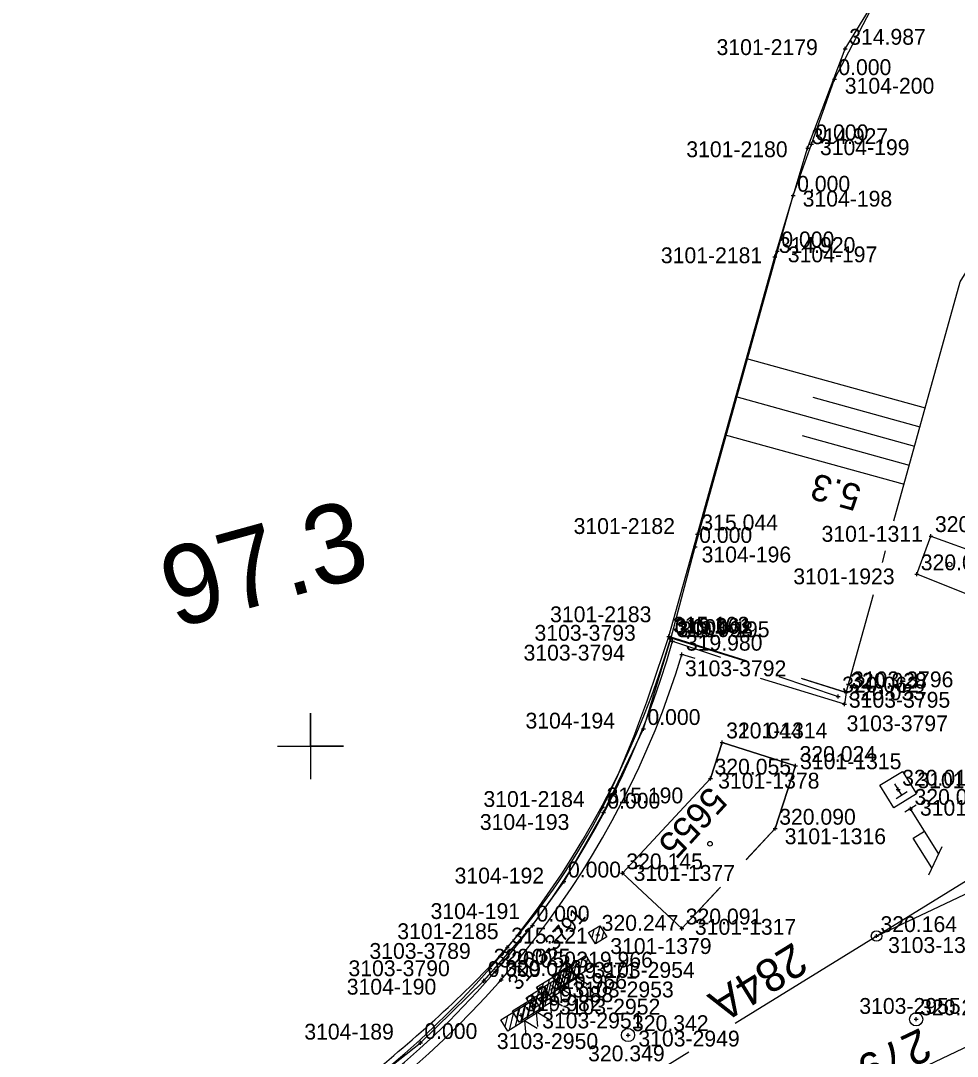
# Model space of a CAD drawing. Extents: x -821875 to -821475, y -1070280 to -1069975.
# Drawn here: x -821810.98 to -821775.51, y -1070211.76 to -1070172.51 of the extents above; entities that cross this region are included whole.
import ezdxf

# ---------------------------------------------------------------- set-up
doc = ezdxf.new("R2010")
doc.units = 0
for name, color, linetype in [('Vrstva 1', 7, 'Continuous'), ('Vrstva 10', 7, 'Continuous'), ('Vrstva 11', 7, 'Continuous'), ('Vrstva 13', 7, 'Continuous'), ('Vrstva 17', 7, 'Continuous'), ('Vrstva 2', 7, 'Continuous'), ('Vrstva 23', 7, 'Continuous'), ('Vrstva 28', 7, 'Continuous'), ('Vrstva 3', 7, 'Continuous'), ('Vrstva 33', 7, 'Continuous'), ('Vrstva 48', 7, 'Continuous'), ('Vrstva 49', 7, 'Continuous'), ('Vrstva 52', 7, 'Continuous'), ('Vrstva 53', 7, 'Continuous'), ('Vrstva 57', 7, 'Continuous'), ('Vrstva 59', 7, 'Continuous'), ('Vrstva 60', 7, 'Continuous'), ('Vrstva 61', 7, 'Continuous'), ('Vrstva 7', 7, 'Continuous')]:
    doc.layers.add(name, color=color, linetype=linetype)

# ---------------------------------------------------------------- blocks, each defined once
blk = doc.blocks.new('BOD')
at = {"layer": 'Vrstva 3'}
for p, q in [((-0.15, 0), (0.15, 0)), ((0, -0.15), (0, 0.15))]:
    blk.add_line(p, q, dxfattribs=at)

msp = doc.modelspace()

# ---------------------------------------------------------------- linework, layer by layer
at = {"layer": 'Vrstva 1'}
msp.add_lwpolyline([(-821801.25, -1070200), (-821800, -1070200), (-821800, -1070198.75), (-821800, -1070200), (-821798.75, -1070200), (-821800, -1070200), (-821800, -1070201.25)], dxfattribs=at)
msp.add_spline([(-821710.276, -1070200.761), (-821741.264, -1070209.238), (-821760.235, -1070214.402), (-821776.338, -1070219.041), (-821794.464, -1070225.772), (-821811.866, -1070233.595), (-821823.5, -1070239.204)], degree=3, dxfattribs=at)
at = {"layer": 'Vrstva 10'}
for p, q in [((-821777.061, -1070202.245), (-821777.487, -1070202.509)), ((-821776.221, -1070204.077), (-821777.274, -1070202.377)), ((-821776.087, -1070203.818), (-821776.595, -1070204.897))]:
    msp.add_line(p, q, dxfattribs=at)
msp.add_lwpolyline([(-821776.475, -1070204.617), (-821777.172, -1070203.491), (-821776.747, -1070203.227)], dxfattribs=at)
at = {"layer": 'Vrstva 11'}
for p, q in [((-821789.267, -1070206.947), (-821789.343, -1070207.271)), ((-821789.042, -1070206.809), (-821789.204, -1070207.495)), ((-821788.903, -1070207.035), (-821788.979, -1070207.356))]:
    msp.add_line(p, q, dxfattribs=at)
msp.add_lwpolyline([(-821788.78, -1070207.233), (-821789.205, -1070207.496), (-821789.468, -1070207.071), (-821789.043, -1070206.808)], close=True, dxfattribs=at)
msp.add_lwpolyline([(-821788.78, -1070207.233), (-821789.205, -1070207.496), (-821789.468, -1070207.071), (-821789.043, -1070206.808), (-821788.78, -1070207.233)], dxfattribs=at)
at = {"layer": 'Vrstva 13'}
for points in [[(-821783.501, -1070196.775), (-821786.426, -1070195.852), (-821786.358, -1070195.896)], [(-821786.358, -1070195.896), (-821783.468, -1070196.798)], [(-821785.434, -1070196.686), (-821785.934, -1070196.534)], [(-821781.361, -1070197.456), (-821779.709, -1070197.971), (-821779.778, -1070198.411), (-821782.954, -1070197.442)], [(-821779.709, -1070197.971), (-821781.407, -1070197.435)]]:
    msp.add_lwpolyline(points, dxfattribs=at)
for centre, radius, start, end in [((-821818.298, -1070186.575), 33.273, 301.8836, 343.7308), ((-821818.089, -1070186.736), 33.615, 301.8138, 343.0522)]:
    msp.add_arc(centre, radius, start, end, dxfattribs=at)
msp.add_spline([(-821797.899, -1070212.619), (-821792.547, -1070207.633), (-821788.936, -1070202.321), (-821786.426, -1070195.852)], degree=3, dxfattribs=at)
at = {"layer": 'Vrstva 17'}
for points in [[(-821785.347, -1070191.975), (-821782.414, -1070181.46), (-821781.172, -1070177.336), (-821779.748, -1070173.57), (-821777.608, -1070170.061), (-821774.963, -1070166.997), (-821771.94, -1070164.191), (-821768.526, -1070161.97), (-821763.149, -1070159.284), (-821721.814, -1070148.42), (-821694.32, -1070141.229), (-821660.419, -1070132.27), (-821642.912, -1070119.833)], [(-821786.426, -1070195.852), (-821785.347, -1070191.975)], [(-821786.289, -1070196.02), (-821784.474, -1070196.628)], [(-821782.264, -1070197.367), (-821780.015, -1070198.12)]]:
    msp.add_lwpolyline(points, dxfattribs=at)
msp.add_arc((-821817.672, -1070187.259), 32.583, 301.1344, 344.4018, dxfattribs=at)
at = {"layer": 'Vrstva 2'}
for points in [[(-821783.916, -1070210.505), (-821764.427, -1070198.469)], [(-821778.563, -1070207.199), (-821763.559, -1070200.088)], [(-821779.893, -1070213.645), (-821778.741, -1070213.109), (-821755.359, -1070201.967)], [(-821792.73, -1070215.95), (-821791.371, -1070215.11), (-821785.674, -1070211.591)]]:
    msp.add_lwpolyline(points, dxfattribs=at)
msp.add_circle((-821778.563, -1070207.199), 0.2, dxfattribs=at)
at = {"layer": 'Vrstva 23'}
for points in [[(-821776.501, -1070192.039), (-821774.553, -1070192.757), (-821775.104, -1070194.254), (-821777.038, -1070193.488), (-821776.501, -1070192.039)], [(-821783.495, -1070204.299), (-821782.4, -1070203.13), (-821781.63, -1070200.75), (-821784.41, -1070199.86), (-821784.85, -1070201.23), (-821788.19, -1070204.82)], [(-821788.19, -1070204.82), (-821785.94, -1070206.91), (-821784.535, -1070205.41)]]:
    msp.add_lwpolyline(points, dxfattribs=at)
at = {"layer": 'Vrstva 28'}
for p, q in [((-821789.922, -1070208.148), (-821790.084, -1070208.836)), ((-821789.696, -1070208.009), (-821789.859, -1070208.696)), ((-821789.511, -1070208.042), (-821789.633, -1070208.557)), ((-821789.372, -1070208.268), (-821789.408, -1070208.418)), ((-821790.598, -1070208.566), (-821790.695, -1070208.979)), ((-821790.51, -1070208.565), (-821790.672, -1070209.253)), ((-821790.373, -1070208.427), (-821790.535, -1070209.115)), ((-821790.284, -1070208.426), (-821790.447, -1070209.113)), ((-821790.147, -1070208.287), (-821790.309, -1070208.975)), ((-821790.099, -1070208.459), (-821790.221, -1070208.974)), ((-821791.186, -1070208.983), (-821791.283, -1070209.396)), ((-821790.961, -1070208.844), (-821791.123, -1070209.532)), ((-821790.903, -1070208.962), (-821791.065, -1070209.65)), ((-821790.735, -1070208.704), (-821790.897, -1070209.392)), ((-821790.677, -1070208.823), (-821790.84, -1070209.51)), ((-821790.823, -1070208.705), (-821790.835, -1070208.753)), ((-821790.492, -1070208.856), (-821790.614, -1070209.371)), ((-821789.96, -1070208.685), (-821789.996, -1070208.835)), ((-821791.579, -1070209.38), (-821791.676, -1070209.793)), ((-821791.354, -1070209.241), (-821791.516, -1070209.929)), ((-821791.411, -1070209.122), (-821791.423, -1070209.17)), ((-821791.199, -1070209.322), (-821791.362, -1070210.009)), ((-821791.128, -1070209.101), (-821791.29, -1070209.789)), ((-821791.014, -1070209.355), (-821791.136, -1070209.87)), ((-821790.353, -1070209.082), (-821790.389, -1070209.232)), ((-821791.876, -1070209.74), (-821792.038, -1070210.428)), ((-821791.865, -1070209.802), (-821792.027, -1070210.49)), ((-821791.804, -1070209.519), (-821791.816, -1070209.567)), ((-821791.65, -1070209.6), (-821791.812, -1070210.288)), ((-821791.639, -1070209.663), (-821791.802, -1070210.35)), ((-821791.425, -1070209.461), (-821791.587, -1070210.149)), ((-821791.454, -1070209.696), (-821791.576, -1070210.211)), ((-821790.875, -1070209.581), (-821790.911, -1070209.731)), ((-821792.541, -1070210.22), (-821792.638, -1070210.633)), ((-821792.316, -1070210.081), (-821792.478, -1070210.769)), ((-821792.326, -1070210.018), (-821792.338, -1070210.066)), ((-821792.09, -1070209.941), (-821792.252, -1070210.629)), ((-821792.101, -1070209.879), (-821792.198, -1070210.292)), ((-821791.315, -1070209.922), (-821791.351, -1070210.072)), ((-821792.766, -1070210.359), (-821792.778, -1070210.407)), ((-821777.085, -1070210.354), (-821777.035, -1070210.354)), ((-821788, -1070210.952), (-821787.95, -1070210.952))]:
    msp.add_line(p, q, dxfattribs=at)
for points in [[(-821789.315, -1070208.361), (-821790.59, -1070209.149), (-821790.853, -1070208.723), (-821789.578, -1070207.935)], [(-821789.903, -1070208.778), (-821791.178, -1070209.566), (-821791.441, -1070209.14), (-821790.166, -1070208.352)], [(-821790.296, -1070209.175), (-821791.571, -1070209.963), (-821791.834, -1070209.537), (-821790.559, -1070208.749)], [(-821790.818, -1070209.674), (-821792.093, -1070210.462), (-821792.356, -1070210.036), (-821791.081, -1070209.248)], [(-821791.258, -1070210.015), (-821792.533, -1070210.803), (-821792.796, -1070210.377), (-821791.521, -1070209.589)]]:
    msp.add_lwpolyline(points, close=True, dxfattribs=at)
for points in [[(-821789.315, -1070208.361), (-821790.59, -1070209.149), (-821790.853, -1070208.723), (-821789.578, -1070207.935), (-821789.315, -1070208.361)], [(-821789.903, -1070208.778), (-821791.178, -1070209.566), (-821791.441, -1070209.14), (-821790.166, -1070208.352), (-821789.903, -1070208.778)], [(-821790.296, -1070209.175), (-821791.571, -1070209.963), (-821791.834, -1070209.537), (-821790.559, -1070208.749), (-821790.296, -1070209.175)], [(-821789.477, -1070209.048), (-821789.953, -1070208.754), (-821789.903, -1070209.311)], [(-821790.818, -1070209.674), (-821792.093, -1070210.462), (-821792.356, -1070210.036), (-821791.081, -1070209.248), (-821790.818, -1070209.674)], [(-821790.065, -1070209.465), (-821790.541, -1070209.171), (-821790.491, -1070209.728)], [(-821791.258, -1070210.015), (-821792.533, -1070210.803), (-821792.796, -1070210.377), (-821791.521, -1070209.589), (-821791.258, -1070210.015)], [(-821790.458, -1070209.862), (-821790.934, -1070209.568), (-821790.884, -1070210.125)], [(-821790.98, -1070210.361), (-821791.456, -1070210.067), (-821791.406, -1070210.624)], [(-821791.42, -1070210.702), (-821791.896, -1070210.408), (-821791.846, -1070210.965)]]:
    msp.add_lwpolyline(points, dxfattribs=at)
for centre in [(-821777.06, -1070210.354), (-821787.975, -1070210.952)]:
    msp.add_circle(centre, 0.25, dxfattribs=at)
at = {"layer": 'Vrstva 33'}
for p, q in [((-821777.611, -1070201.863), (-821777.875, -1070201.437)), ((-821777.398, -1070201.731), (-821777.824, -1070201.995))]:
    msp.add_line(p, q, dxfattribs=at)
msp.add_lwpolyline([(-821777.054, -1070201.812), (-821777.905, -1070202.339), (-821778.432, -1070201.488), (-821777.581, -1070200.961), (-821777.054, -1070201.812)], dxfattribs=at)
at = {"layer": 'Vrstva 48'}
for p, q in [((-821783.488, -1070185.31), (-821776.721, -1070187.184)), ((-821783.891, -1070186.754), (-821777.122, -1070188.629)), ((-821780.982, -1070186.782), (-821776.921, -1070187.907)), ((-821784.294, -1070188.199), (-821777.522, -1070190.074)), ((-821781.384, -1070188.227), (-821777.322, -1070189.352))]:
    msp.add_line(p, q, dxfattribs=at)
at = {"layer": 'Vrstva 49'}
for points in [[(-821777.907, -1070191.463), (-821775.399, -1070182.41), (-821768.529, -1070171.311), (-821736.653, -1070158.01)], [(-821778.343, -1070193.038), (-821778.222, -1070192.6)], [(-821779.709, -1070197.971), (-821778.68, -1070194.255)]]:
    msp.add_lwpolyline(points, dxfattribs=at)
at = {"layer": 'Vrstva 52'}
for points in [[(-821788.19, -1070204.82), (-821784.85, -1070201.23), (-821784.41, -1070199.86), (-821781.63, -1070200.75), (-821782.4, -1070203.13), (-821783.505, -1070204.31)], [(-821784.479, -1070205.35), (-821785.94, -1070206.91), (-821788.19, -1070204.82)]]:
    msp.add_lwpolyline(points, dxfattribs=at)
at = {"layer": 'Vrstva 53'}
msp.add_lwpolyline([(-821817.612, -1070227.046), (-821811.14, -1070222.26), (-821798.18, -1070213.11), (-821795.84, -1070211.25), (-821793.44, -1070208.9), (-821791.59, -1070206.8), (-821790.4, -1070205.13), (-821788.91, -1070202.52), (-821787.39, -1070199.35), (-821786.35, -1070195.94), (-821785.43, -1070192.45), (-821782.32, -1070181.25), (-821781.72, -1070179.14), (-821781.03, -1070177.19), (-821780.16, -1070174.72), (-821778.53, -1070171.61)], dxfattribs=at)
at = {"layer": 'Vrstva 59'}
for centre in [(-821775.794, -1070193.119), (-821784.87, -1070203.703)]:
    msp.add_circle(centre, 0.0873, dxfattribs=at)

# ---------------------------------------------------------------- block references
at = {"layer": 'Vrstva 60', "xscale": 0.5, "yscale": 0.5}
for p in [(-821779.748, -1070173.57), (-821780.16, -1070174.72), (-821781.172, -1070177.336), (-821781.03, -1070177.19), (-821781.72, -1070179.14), (-821782.32, -1070181.25), (-821782.414, -1070181.46), (-821785.347, -1070191.975), (-821776.501, -1070192.039), (-821785.43, -1070192.45), (-821777.038, -1070193.488), (-821786.426, -1070195.852), (-821786.358, -1070195.896), (-821786.35, -1070195.94), (-821786.289, -1070196.02), (-821785.934, -1070196.534), (-821780.015, -1070198.12), (-821779.709, -1070197.971), (-821779.778, -1070198.411), (-821787.39, -1070199.35), (-821784.41, -1070199.86), (-821781.63, -1070200.75), (-821784.85, -1070201.23), (-821777.743, -1070201.65), (-821788.936, -1070202.321), (-821777.274, -1070202.377), (-821788.91, -1070202.52), (-821782.4, -1070203.13), (-821788.19, -1070204.82), (-821790.4, -1070205.13), (-821791.59, -1070206.8), (-821789.124, -1070207.152), (-821785.94, -1070206.91), (-821778.563, -1070207.199), (-821792.547, -1070207.633), (-821793.213, -1070208.433), (-821793, -1070208.541), (-821790.084, -1070208.542), (-821793.44, -1070208.9), (-821792.783, -1070208.861), (-821790.672, -1070208.959), (-821791.065, -1070209.356), (-821791.587, -1070209.855), (-821792.027, -1070210.196), (-821777.06, -1070210.354), (-821787.975, -1070210.952), (-821795.84, -1070211.25)]:
    msp.add_blockref('BOD', p, dxfattribs=at)

# ---------------------------------------------------------------- texts
at = {"layer": 'Vrstva 11'}
msp.add_text('284A', height=1.25, rotation=211.7161, dxfattribs=at).set_placement((-821781.708, -1070207.409))
at = {"layer": 'Vrstva 2'}
msp.add_text('279', height=1.25, rotation=205.4788, dxfattribs=at).set_placement((-821776.896, -1070210.661))
at = {"layer": 'Vrstva 48'}
msp.add_text('5.3', height=1, rotation=164.5239, dxfattribs=at).set_placement((-821779.082, -1070190.146))
at = {"layer": 'Vrstva 57'}
msp.add_text('5655', height=1, rotation=227.53, dxfattribs=at).set_placement((-821784.887, -1070201.472))
at = {"layer": 'Vrstva 60'}
for s, p in [('3101-2179', (-821784.623, -1070173.811)), ('3104-200', (-821779.766, -1070175.275)), ('3101-2180', (-821785.768, -1070177.682)), ('3104-199', (-821780.705, -1070177.605)), ('3104-198', (-821781.361, -1070179.555)), ('3101-2181', (-821786.731, -1070181.7)), ('3104-197', (-821781.925, -1070181.665)), ('3101-2182', (-821790.037, -1070191.962)), ('3101-1311', (-821780.645, -1070192.257)), ('3104-196', (-821785.188, -1070193.039)), ('3101-1923', (-821781.716, -1070193.869)), ('3101-2183', (-821790.927, -1070195.306)), ('3104-195', (-821786.007, -1070195.875)), ('3103-3793', (-821791.519, -1070196.009)), ('3103-3794', (-821791.933, -1070196.76)), ('3103-3792', (-821785.817, -1070197.354)), ('3103-3796', (-821779.489, -1070197.772)), ('3103-3795', (-821779.609, -1070198.546)), ('3104-194', (-821791.859, -1070199.336)), ('3103-3797', (-821779.697, -1070199.44)), ('3101-1314', (-821784.26, -1070199.707)), ('3101-1315', (-821781.457, -1070200.876)), ('3101-1378', (-821784.562, -1070201.611)), ('3101-1319', (-821777.016, -1070201.596)), ('3101-2184', (-821793.452, -1070202.307)), ('3101-1318', (-821776.919, -1070202.638)), ('3104-193', (-821793.588, -1070203.179)), ('3101-1316', (-821782.041, -1070203.719)), ('3104-192', (-821794.544, -1070205.209)), ('3101-1377', (-821787.761, -1070205.108)), ('3104-191', (-821795.455, -1070206.554)), ('3101-2185', (-821796.714, -1070207.318)), ('3101-1317', (-821785.442, -1070207.151)), ('3103-3789', (-821797.77, -1070208.065)), ('3101-1379', (-821788.648, -1070207.88)), ('3103-1344', (-821778.125, -1070207.841)), ('3103-3790', (-821798.564, -1070208.721)), ('3103-2954', (-821789.285, -1070208.784)), ('3104-190', (-821798.629, -1070209.42)), ('3103-2953', (-821790.081, -1070209.525)), ('3103-2952', (-821790.59, -1070210.177)), ('3103-2955', (-821779.215, -1070210.149)), ('3103-2951', (-821791.228, -1070210.699)), ('3104-189', (-821800.236, -1070211.124)), ('3103-2950', (-821792.945, -1070211.481)), ('3103-2949', (-821787.584, -1070211.386))]:
    msp.add_text(s, height=0.6, dxfattribs=at).set_placement(p)
msp.add_text('3103-3791', height=0.6, rotation=47.128, dxfattribs=at).set_placement((-821792.149, -1070209.295))
at = {"layer": 'Vrstva 61'}
for s, p in [('314.987', (-821779.598, -1070173.42)), ('0.000', (-821780.01, -1070174.57)), ('0.000', (-821780.88, -1070177.04)), ('314.927', (-821781.022, -1070177.186)), ('0.000', (-821781.57, -1070178.99)), ('314.920', (-821782.264, -1070181.31)), ('0.000', (-821782.17, -1070181.1)), ('315.044', (-821785.197, -1070191.825)), ('320.055', (-821776.351, -1070191.889)), ('0.000', (-821785.28, -1070192.3)), ('320.050', (-821776.888, -1070193.338)), ('315.103', (-821786.276, -1070195.702)), ('319.961', (-821786.208, -1070195.746)), ('0.000', (-821786.2, -1070195.79)), ('319.998', (-821786.139, -1070195.87)), ('319.980', (-821785.784, -1070196.384)), ('320.028', (-821779.559, -1070197.821)), ('320.062', (-821779.865, -1070197.97)), ('320.053', (-821779.628, -1070198.261)), ('0.000', (-821787.24, -1070199.2)), ('320.044', (-821784.26, -1070199.71)), ('320.024', (-821781.48, -1070200.6)), ('320.055', (-821784.7, -1070201.08)), ('320.014', (-821777.593, -1070201.5)), ('315.190', (-821788.786, -1070202.171)), ('0.000', (-821788.76, -1070202.37)), ('320.021', (-821777.124, -1070202.227)), ('320.090', (-821782.25, -1070202.98)), ('320.145', (-821788.04, -1070204.67)), ('0.000', (-821790.25, -1070204.98)), ('0.000', (-821791.44, -1070206.65)), ('320.091', (-821785.79, -1070206.76)), ('320.247', (-821788.974, -1070207.002)), ('320.164', (-821778.413, -1070207.049)), ('315.221', (-821792.397, -1070207.483)), ('320.025', (-821793.063, -1070208.283)), ('320.050', (-821792.85, -1070208.391)), ('319.966', (-821789.934, -1070208.392)), ('0.000', (-821793.29, -1070208.75)), ('320.046', (-821792.633, -1070208.711)), ('319.971', (-821790.522, -1070208.809)), ('319.966', (-821790.915, -1070209.206)), ('319.982', (-821791.877, -1070210.046)), ('319.988', (-821791.437, -1070209.705)), ('320.241', (-821776.91, -1070210.204)), ('320.342', (-821787.825, -1070210.802)), ('0.000', (-821795.69, -1070211.1)), ('320.349', (-821789.488, -1070211.947))]:
    msp.add_text(s, height=0.6, dxfattribs=at).set_placement(p)
at = {"layer": 'Vrstva 7'}
msp.add_text('97.3', height=3, rotation=15.4527, dxfattribs=at).set_placement((-821805.148, -1070195.563))

doc.saveas('drawing.dxf')
